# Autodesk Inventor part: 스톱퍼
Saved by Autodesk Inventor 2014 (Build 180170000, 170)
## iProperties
Created: 2025-06
Part Number: 스톱퍼
Material: 일반
Document SubType Name: Modeling
Designer: dg
Density: 1 g/cm^3
Appearance: 기본값
Author: dg
Author: jhkim
Creation Date: 2025-05-27
Sending System: Autodesk Inventor 2026
Preprocessor: ST-DEVELOPER v20.1
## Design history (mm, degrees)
node "스톱퍼1"
node "솔리드1"
node "기준1"
